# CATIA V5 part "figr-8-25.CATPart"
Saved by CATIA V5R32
Part number: Part1
Bounding box of the stored display mesh (mm): x -50 to 50, y -62.5 to 62.5, z 0 to 10
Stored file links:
  D:\PROJECTS\Project 2022\CATIA V5 6R 2022\Resources\Part Files\c08_catia_v5_6r2022_prt\figr-8-25.CATPart
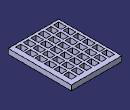
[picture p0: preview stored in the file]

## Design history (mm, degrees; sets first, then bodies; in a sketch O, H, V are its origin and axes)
Body1 (main body)
  Sketch1 on xy-plane, origin (0, 0, 0), H (1, 0, 0), V (0, 1, 0)
    line L1 (-50, 62.5) -> (50, 62.5)
    line L2 (50, 62.5) -> (50, -62.5)
    line L3 (50, -62.5) -> (-50, -62.5)
    line L4 (-50, -62.5) -> (-50, 62.5)
    axis line L5 (50, -62.5) -> (-50, 62.5)
    length L3 = 100
    length L2 = 125
    horizontal: L1 H, L3 H
    vertical: L2 V, L4 V
    midpoint: O L5
  Pad1: profile Sketch1, direction (0, 0, 1), length 10
  Sketch2 on face of Pad1, origin (0, 0, 10), H (1, 0, 0), V (0, 1, 0)
    line L1 (40, -57.5) -> (30, -57.5)
    line L2 (30, -57.5) -> (30, -42.5)
    line L3 (30, -42.5) -> (40, -42.5)
    line L4 (40, -42.5) -> (40, -57.5)
    reference projected line E1 (-50, -62.5) -> (50, -62.5) from edge [face of Pad1 | face of Pad1]
    reference projected line E2 (50, -62.5) -> (50, 62.5) from edge [face of Pad1 | face of Pad1]
    length L1 = 10
    length L4 = 15
    distance L1 E1 = 5
    distance L4 E2 = 10
    horizontal: L1 H, L3 H
    vertical: L2 V, L4 V
  Pocket1: profile Sketch2, direction (0, 0, -1), through (limit type 3)
  RectPattern1: of Pocket1, direction 1 instances 6, spacing 19, along edge [face of Pad1 | face of Pad1], direction 2 instances 6, spacing 15, along edge [face of Pad1 | face of Pad1] reversed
